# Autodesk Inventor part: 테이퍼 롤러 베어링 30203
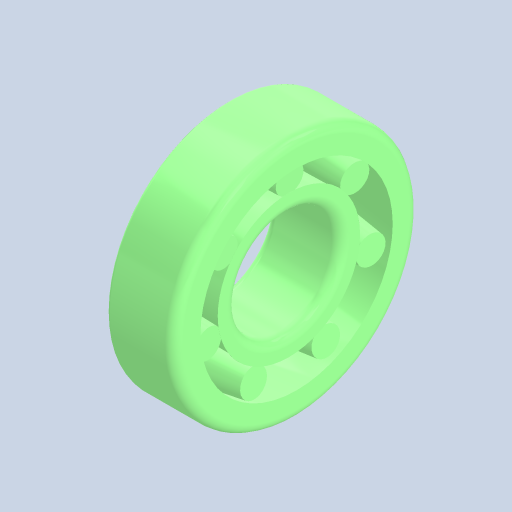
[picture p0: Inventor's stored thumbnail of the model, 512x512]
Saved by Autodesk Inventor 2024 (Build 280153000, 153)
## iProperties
Created: 2026-01
Part Number: 테이퍼 롤러 베어링 30203
Material: 강철, 연강
Description: 테이퍼 롤러 베어링
Document SubType Name: Modeling
Designer: 2-10
Density: 7.85 g/cm^3
Appearance: 기본값
Author: jhkim
Sending System: Autodesk Inventor 2026
Preprocessor: ST-DEVELOPER v20.1
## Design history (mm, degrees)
feature "Solid1"
feature "Solid1:1"
node "솔리드1"
node "솔리드2"
